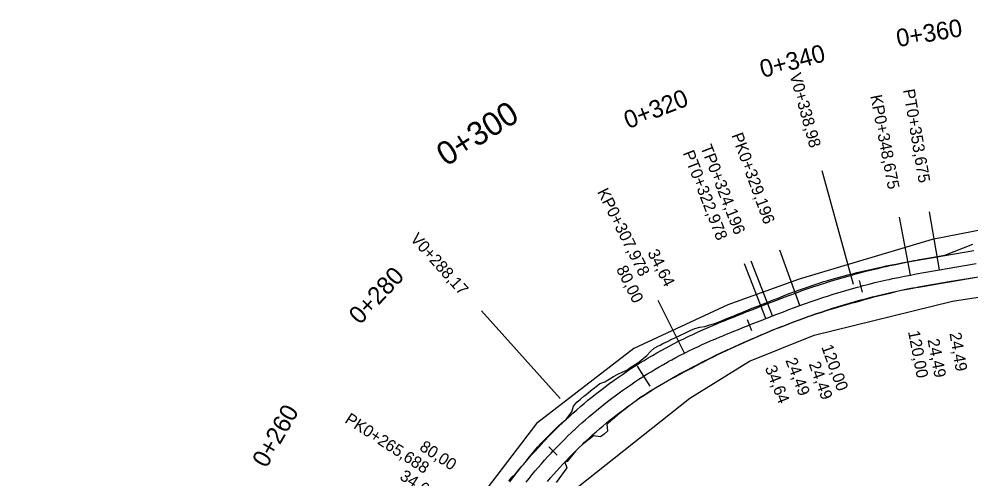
# Model space of a CAD drawing. Extents: x -636600 to -628587, y -1090963 to -1085869.
# Drawn here: x -635071.7 to -634910.1, y -1088714.1 to -1088635.9 of the extents above; entities that cross this region are included whole.
import ezdxf

# ---------------------------------------------------------------- set-up
doc = ezdxf.new("R2010")
doc.units = 0
for name, color, linetype in [('01_PARCELY_NÁVRH_PC', 7, 'Continuous'), ('HEKTOMETRY100', 7, 'Continuous'), ('HEKTOMETRY20', 7, 'Continuous'), ('HL_BODY', 7, 'Continuous'), ('POLOMERY', 7, 'Continuous'), ('situace_osa', 7, 'Continuous'), ('situace_těleso', 7, 'Continuous'), ('situace_vozovka', 7, 'Continuous'), ('VRCHOLY', 7, 'Continuous')]:
    doc.layers.add(name, color=color, linetype=linetype)

msp = doc.modelspace()

# ---------------------------------------------------------------- linework, layer by layer
at = {"layer": '01_PARCELY_NÁVRH_PC'}
for points in [[(-634861.29, -1088662.55), (-634916.65, -1088673.39), (-634939.28, -1088680.12), (-634951.36, -1088684.51), (-634967.33, -1088691.91), (-634983.87, -1088704.68), (-634995.51, -1088719.97), (-635021.98, -1088768.35), (-635040.92, -1088797.21), (-635078.05, -1088850.49), (-635098.99, -1088876.35), (-635105.07, -1088879.12), (-635110.88, -1088888.39), (-635119.1, -1088902.88), (-635126.27, -1088922.85), (-635127.59, -1088927.58), (-635130.38, -1088937.08), (-635132.64, -1088944.55), (-635134.08, -1088948.9), (-635141.78, -1088965.52), (-635145.13, -1088972.03), (-635147.95, -1088976.12), (-635154.73, -1088985.94)], [(-635153.56, -1088999.63), (-635131.9, -1088967.9), (-635114.47, -1088929.52), (-635113.55, -1088922.94), (-635105.31, -1088903.63), (-635101.54, -1088905.22), (-635094.81, -1088889.19), (-635080.24, -1088867.26), (-635022.41, -1088789.13), (-635007.04, -1088763.27), (-634984.89, -1088721.83), (-634957.8, -1088700.36), (-634947.7, -1088694.08), (-634936.69, -1088689.67), (-634913.24, -1088683.86), (-634889.39, -1088680.18)]]:
    msp.add_lwpolyline(points, dxfattribs=at)
at = {"layer": 'HEKTOMETRY100'}
msp.add_lwpolyline([(-634966.74, -1088694.94), (-634964.59, -1088698.32)], dxfattribs=at)
at = {"layer": 'HEKTOMETRY20'}
for points in [[(-634929.08, -1088680.38), (-634928.57, -1088682.31)], [(-634948.07, -1088686.98), (-634947.34, -1088688.84)], [(-634981.78, -1088708.64), (-634980.32, -1088710.02)]]:
    msp.add_lwpolyline(points, dxfattribs=at)
at = {"layer": 'HL_BODY'}
for points in [[(-634915.45, -1088678.55), (-634917.11, -1088668.69)], [(-634920.37, -1088679.42), (-634922.24, -1088669.59)], [(-634939.13, -1088684.6), (-634942.56, -1088675.21)], [(-634944.93, -1088686.82), (-634948.56, -1088677.51)], [(-634943.8, -1088686.38), (-634947.43, -1088677.06)], [(-634958.73, -1088692.7), (-634963.21, -1088683.77)]]:
    msp.add_lwpolyline(points, dxfattribs=at)
at = {"layer": 'POLOMERY'}
for points in [[(-634915.45, -1088678.55), (-634917.11, -1088668.69)], [(-634920.37, -1088679.42), (-634922.24, -1088669.59)], [(-634939.13, -1088684.6), (-634942.56, -1088675.21)], [(-634944.93, -1088686.82), (-634948.56, -1088677.51)], [(-634943.8, -1088686.38), (-634947.43, -1088677.06)], [(-634958.73, -1088692.7), (-634963.21, -1088683.77)]]:
    msp.add_lwpolyline(points, dxfattribs=at)
at = {"layer": 'situace_osa'}
msp.add_lwpolyline([(-634985.62, -1088714.62), (-634985.11, -1088713.99), (-634984.6, -1088713.35), (-634984.36, -1088713.07), (-634984.08, -1088712.73), (-634983.55, -1088712.11), (-634983.02, -1088711.49), (-634982.48, -1088710.89), (-634981.93, -1088710.28), (-634981.38, -1088709.68), (-634981.05, -1088709.33), (-634980.82, -1088709.09), (-634980.26, -1088708.5), (-634979.69, -1088707.92), (-634979.12, -1088707.35), (-634978.54, -1088706.78), (-634977.95, -1088706.22), (-634977.51, -1088705.8), (-634977.36, -1088705.66), (-634976.76, -1088705.11), (-634976.16, -1088704.56), (-634975.55, -1088704.02), (-634974.93, -1088703.49), (-634974.31, -1088702.96), (-634973.75, -1088702.5), (-634973.69, -1088702.44), (-634973.06, -1088701.93), (-634972.42, -1088701.42), (-634971.78, -1088700.92), (-634971.14, -1088700.43), (-634970.48, -1088699.94), (-634969.83, -1088699.46), (-634969.8, -1088699.44), (-634969.17, -1088698.98), (-634968.5, -1088698.52), (-634967.83, -1088698.06), (-634967.16, -1088697.6), (-634966.48, -1088697.15), (-634965.8, -1088696.71), (-634965.67, -1088696.63), (-634965.11, -1088696.28), (-634964.41, -1088695.85), (-634963.72, -1088695.44), (-634963.02, -1088695.02), (-634962.31, -1088694.62), (-634961.6, -1088694.22), (-634961.36, -1088694.09), (-634960.89, -1088693.83), (-634960.17, -1088693.45), (-634959.45, -1088693.07), (-634958.73, -1088692.7), (-634958.39, -1088692.53), (-634957.98, -1088692.33), (-634957.23, -1088691.97), (-634956.91, -1088691.82), (-634956.48, -1088691.61), (-634955.72, -1088691.26), (-634954.96, -1088690.92), (-634954.2, -1088690.58), (-634953.43, -1088690.25), (-634952.67, -1088689.92), (-634952.34, -1088689.79), (-634951.9, -1088689.6), (-634951.13, -1088689.28), (-634950.36, -1088688.97), (-634949.58, -1088688.66), (-634948.81, -1088688.35), (-634948.04, -1088688.04), (-634947.71, -1088687.91), (-634947.26, -1088687.73), (-634946.48, -1088687.43), (-634945.71, -1088687.13), (-634944.93, -1088686.82), (-634944.59, -1088686.69), (-634943.8, -1088686.38), (-634943.05, -1088686.09), (-634942.87, -1088686.02), (-634941.93, -1088685.66), (-634941, -1088685.3), (-634940.06, -1088684.95), (-634939.13, -1088684.6), (-634938.37, -1088684.32), (-634938.16, -1088684.25), (-634937.19, -1088683.91), (-634936.22, -1088683.58), (-634935.25, -1088683.26), (-634934.28, -1088682.94), (-634933.63, -1088682.74), (-634933.3, -1088682.63), (-634932.32, -1088682.34), (-634931.33, -1088682.05), (-634930.35, -1088681.76), (-634929.36, -1088681.49), (-634928.83, -1088681.35), (-634928.37, -1088681.23), (-634927.38, -1088680.97), (-634926.38, -1088680.72), (-634925.38, -1088680.48), (-634924.39, -1088680.25), (-634923.97, -1088680.16), (-634923.38, -1088680.03), (-634922.38, -1088679.82), (-634921.38, -1088679.61), (-634920.37, -1088679.42), (-634919.39, -1088679.23), (-634919.07, -1088679.17), (-634918.4, -1088679.06), (-634917.42, -1088678.88), (-634916.43, -1088678.72), (-634915.45, -1088678.55), (-634914.14, -1088678.33), (-634909.21, -1088677.49)], dxfattribs=at)
at = {"layer": 'situace_těleso'}
for points in [[(-634988.53, -1088714.46), (-634988.03, -1088713.79), (-634987.48, -1088713.28), (-634987.41, -1088713.2), (-634986.88, -1088712.56), (-634986.34, -1088711.92), (-634986.09, -1088711.63), (-634985.8, -1088711.28), (-634985.28, -1088710.63), (-634984.75, -1088709.98), (-634984.22, -1088709.33), (-634983.68, -1088708.69), (-634983.13, -1088708.06), (-634982.77, -1088707.71), (-634982.53, -1088707.47), (-634981.95, -1088706.87), (-634981.36, -1088706.28), (-634980.76, -1088705.69), (-634980.16, -1088705.11), (-634979.53, -1088704.56), (-634979.06, -1088704.15), (-634978.9, -1088704.01), (-634978.36, -1088703.35), (-634977.84, -1088702.68), (-634977.59, -1088701.69), (-634977.02, -1088701.05), (-634976.38, -1088700.51), (-634975.8, -1088700.02), (-634975.73, -1088699.96), (-634975.08, -1088699.43), (-634974.42, -1088698.9), (-634973.75, -1088698.37), (-634973.08, -1088697.85), (-634972.24, -1088697.58), (-634971.52, -1088697.12), (-634971.49, -1088697.11), (-634970.8, -1088696.69), (-634970.05, -1088696.29), (-634969.29, -1088695.92), (-634968.51, -1088695.57), (-634967.82, -1088695.1), (-634967.11, -1088694.65), (-634966.97, -1088694.57), (-634966.41, -1088694.19), (-634965.77, -1088693.62), (-634965.12, -1088693.08), (-634964.52, -1088692.43), (-634963.88, -1088691.85), (-634963.13, -1088691.47), (-634962.87, -1088691.33), (-634962.38, -1088691.08), (-634961.62, -1088690.7), (-634960.86, -1088690.33), (-634960.1, -1088689.96), (-634959.74, -1088689.8), (-634959.32, -1088689.6), (-634958.54, -1088689.23), (-634958.2, -1088689.08), (-634957.75, -1088688.88), (-634956.97, -1088688.53), (-634956.13, -1088688.3), (-634955.25, -1088688.18), (-634954.44, -1088687.9), (-634953.63, -1088687.64), (-634953.29, -1088687.53), (-634952.83, -1088687.36), (-634952.05, -1088687.04), (-634951.27, -1088686.72), (-634950.49, -1088686.41), (-634949.71, -1088686.09), (-634948.93, -1088685.77), (-634948.6, -1088685.63), (-634948.16, -1088685.45), (-634947.38, -1088685.14), (-634946.6, -1088684.83), (-634945.83, -1088684.52), (-634945.49, -1088684.39), (-634944.7, -1088684.07), (-634943.95, -1088683.77), (-634943.77, -1088683.7), (-634942.83, -1088683.33), (-634941.89, -1088682.96), (-634940.95, -1088682.59), (-634939.99, -1088682.23), (-634939.22, -1088681.94), (-634939.01, -1088681.86), (-634938.02, -1088681.53), (-634937.03, -1088681.2), (-634936.03, -1088680.87), (-634935.04, -1088680.55), (-634934.38, -1088680.34), (-634934.04, -1088680.24), (-634933.03, -1088679.94), (-634932.02, -1088679.68), (-634931.01, -1088679.41), (-634929.99, -1088679.16), (-634929.45, -1088679.02), (-634928.98, -1088678.91), (-634927.96, -1088678.67), (-634926.94, -1088678.43), (-634925.92, -1088678.2), (-634924.9, -1088677.98), (-634924.47, -1088677.89), (-634923.88, -1088677.77), (-634922.85, -1088677.56), (-634921.83, -1088677.36), (-634920.8, -1088677.17), (-634919.8, -1088676.98), (-634919.47, -1088676.93), (-634918.8, -1088676.81), (-634917.81, -1088676.63), (-634916.81, -1088676.47), (-634915.83, -1088676.29), (-634914.52, -1088676.06), (-634909.77, -1088674.19)], [(-634908.82, -1088679.81), (-634913.75, -1088680.62), (-634915.06, -1088680.85), (-634916.04, -1088681.02), (-634917.02, -1088681.19), (-634918, -1088681.37), (-634918.65, -1088681.49), (-634918.96, -1088681.55), (-634919.94, -1088681.68), (-634920.93, -1088681.83), (-634921.91, -1088682.07), (-634922.89, -1088682.3), (-634923.46, -1088682.44), (-634923.87, -1088682.54), (-634924.84, -1088682.78), (-634925.82, -1088683.02), (-634926.79, -1088683.27), (-634927.76, -1088683.53), (-634928.21, -1088683.65), (-634928.73, -1088683.79), (-634929.7, -1088684.07), (-634930.67, -1088684.34), (-634931.63, -1088684.63), (-634932.6, -1088684.91), (-634932.92, -1088685), (-634933.56, -1088685.19), (-634934.52, -1088685.48), (-634935.48, -1088685.78), (-634936.44, -1088686.09), (-634937.39, -1088686.42), (-634937.59, -1088686.49), (-634938.34, -1088686.75), (-634939.26, -1088687.08), (-634940.19, -1088687.43), (-634941.11, -1088687.79), (-634942.04, -1088688.15), (-634942.22, -1088688.22), (-634942.97, -1088688.51), (-634943.76, -1088688.82), (-634944.1, -1088688.96), (-634944.87, -1088689.29), (-634945.63, -1088689.61), (-634946.39, -1088689.94), (-634946.83, -1088690.13), (-634947.15, -1088690.27), (-634947.91, -1088690.6), (-634948.67, -1088690.94), (-634949.42, -1088691.28), (-634950.17, -1088691.62), (-634950.91, -1088691.96), (-634951.34, -1088692.16), (-634951.66, -1088692.31), (-634952.4, -1088692.66), (-634953.13, -1088693.01), (-634953.86, -1088693.37), (-634954.59, -1088693.74), (-634955.31, -1088694.1), (-634955.72, -1088694.32), (-634956.03, -1088694.48), (-634956.74, -1088694.86), (-634957.13, -1088695.07), (-634957.45, -1088695.23), (-634958.15, -1088695.59), (-634958.84, -1088695.96), (-634959.54, -1088696.33), (-634959.99, -1088696.58), (-634960.22, -1088696.71), (-634960.91, -1088697.08), (-634961.6, -1088697.46), (-634962.29, -1088697.84), (-634962.96, -1088698.24), (-634963.64, -1088698.64), (-634964.18, -1088698.97), (-634964.31, -1088699.05), (-634964.98, -1088699.46), (-634965.64, -1088699.89), (-634966.29, -1088700.32), (-634966.93, -1088700.78), (-634967.56, -1088701.25), (-634968.16, -1088701.7), (-634968.18, -1088701.72), (-634968.8, -1088702.21), (-634969.42, -1088702.7), (-634970.03, -1088703.19), (-634970.63, -1088703.69), (-634971.23, -1088704.2), (-634971.82, -1088704.71), (-634971.89, -1088704.76), (-634971.79, -1088705.97), (-634972.39, -1088706.46), (-634972.98, -1088706.95), (-634974.2, -1088706.75), (-634974.82, -1088707.24), (-634975.42, -1088707.74), (-634975.58, -1088707.86), (-634976.03, -1088708.24), (-634976.62, -1088708.75), (-634977.15, -1088709.33), (-634977.67, -1088709.93), (-634978.17, -1088710.53), (-634978.67, -1088711.14), (-634979.02, -1088711.24), (-634978.68, -1088712.2), (-634979.15, -1088712.82), (-634979.61, -1088713.45), (-634980.07, -1088714.07), (-634980.53, -1088714.7)]]:
    msp.add_lwpolyline(points, dxfattribs=at)
at = {"layer": 'situace_vozovka'}
for points in [[(-634988.41, -1088714.55), (-634987.9, -1088713.89), (-634987.45, -1088713.31), (-634987.38, -1088713.23), (-634986.86, -1088712.57), (-634986.33, -1088711.92), (-634986.09, -1088711.64), (-634985.8, -1088711.28), (-634985.26, -1088710.64), (-634984.71, -1088710.01), (-634984.16, -1088709.39), (-634983.59, -1088708.77), (-634983.03, -1088708.15), (-634982.69, -1088707.79), (-634982.46, -1088707.54), (-634981.88, -1088706.94), (-634981.29, -1088706.34), (-634980.7, -1088705.75), (-634980.1, -1088705.16), (-634979.5, -1088704.59), (-634979.05, -1088704.16), (-634978.89, -1088704.01), (-634978.28, -1088703.45), (-634977.66, -1088702.89), (-634977.03, -1088702.33), (-634976.4, -1088701.78), (-634975.76, -1088701.24), (-634975.19, -1088700.76), (-634975.12, -1088700.71), (-634974.47, -1088700.18), (-634973.82, -1088699.66), (-634973.16, -1088699.14), (-634972.49, -1088698.63), (-634971.83, -1088698.13), (-634971.15, -1088697.64), (-634971.12, -1088697.62), (-634970.47, -1088697.15), (-634969.79, -1088696.67), (-634969.1, -1088696.2), (-634968.41, -1088695.73), (-634967.71, -1088695.27), (-634967, -1088694.82), (-634966.87, -1088694.73), (-634966.3, -1088694.37), (-634965.58, -1088693.93), (-634964.87, -1088693.5), (-634964.15, -1088693.08), (-634963.42, -1088692.66), (-634962.69, -1088692.25), (-634962.45, -1088692.12), (-634961.96, -1088691.85), (-634961.22, -1088691.46), (-634960.48, -1088691.07), (-634959.74, -1088690.69), (-634959.39, -1088690.52), (-634958.97, -1088690.31), (-634958.2, -1088689.94), (-634957.87, -1088689.78), (-634957.43, -1088689.57), (-634956.65, -1088689.22), (-634955.88, -1088688.87), (-634955.1, -1088688.52), (-634954.32, -1088688.18), (-634953.54, -1088687.85), (-634953.21, -1088687.71), (-634952.76, -1088687.52), (-634951.98, -1088687.2), (-634951.2, -1088686.88), (-634950.42, -1088686.57), (-634949.64, -1088686.26), (-634948.86, -1088685.95), (-634948.53, -1088685.82), (-634948.08, -1088685.64), (-634947.3, -1088685.33), (-634946.53, -1088685.03), (-634945.75, -1088684.73), (-634945.4, -1088684.59), (-634944.61, -1088684.29), (-634943.86, -1088683.99), (-634943.68, -1088683.92), (-634942.74, -1088683.56), (-634941.8, -1088683.2), (-634940.85, -1088682.84), (-634939.9, -1088682.49), (-634939.13, -1088682.21), (-634938.92, -1088682.13), (-634937.93, -1088681.78), (-634936.94, -1088681.45), (-634935.95, -1088681.12), (-634934.96, -1088680.8), (-634934.3, -1088680.59), (-634933.96, -1088680.48), (-634932.96, -1088680.18), (-634931.96, -1088679.88), (-634930.96, -1088679.6), (-634929.95, -1088679.32), (-634929.41, -1088679.17), (-634928.94, -1088679.05), (-634927.93, -1088678.79), (-634926.92, -1088678.54), (-634925.9, -1088678.29), (-634924.88, -1088678.06), (-634924.46, -1088677.96), (-634923.86, -1088677.83), (-634922.84, -1088677.62), (-634921.82, -1088677.41), (-634920.79, -1088677.21), (-634919.79, -1088677.02), (-634919.47, -1088676.96), (-634918.8, -1088676.84), (-634917.8, -1088676.67), (-634916.81, -1088676.5), (-634915.82, -1088676.33), (-634914.52, -1088676.11), (-634909.59, -1088675.27)], [(-634981.98, -1088714.49), (-634981.47, -1088713.89), (-634980.96, -1088713.3), (-634980.43, -1088712.71), (-634979.91, -1088712.13), (-634979.38, -1088711.55), (-634979.06, -1088711.21), (-634978.84, -1088710.98), (-634978.29, -1088710.41), (-634977.74, -1088709.85), (-634977.19, -1088709.3), (-634976.63, -1088708.75), (-634976.06, -1088708.2), (-634975.64, -1088707.8), (-634975.49, -1088707.66), (-634974.91, -1088707.13), (-634974.33, -1088706.6), (-634973.74, -1088706.08), (-634973.15, -1088705.57), (-634972.55, -1088705.06), (-634972.01, -1088704.61), (-634971.95, -1088704.56), (-634971.34, -1088704.06), (-634970.72, -1088703.57), (-634970.1, -1088703.09), (-634969.48, -1088702.61), (-634968.85, -1088702.14), (-634968.22, -1088701.68), (-634968.19, -1088701.66), (-634967.58, -1088701.22), (-634966.94, -1088700.77), (-634966.29, -1088700.32), (-634965.64, -1088699.88), (-634964.98, -1088699.45), (-634964.32, -1088699.03), (-634964.2, -1088698.94), (-634963.66, -1088698.61), (-634962.99, -1088698.19), (-634962.32, -1088697.79), (-634961.64, -1088697.39), (-634960.96, -1088697), (-634960.27, -1088696.62), (-634960.04, -1088696.49), (-634959.59, -1088696.24), (-634958.89, -1088695.87), (-634958.2, -1088695.51), (-634957.5, -1088695.15), (-634957.17, -1088694.99), (-634956.78, -1088694.78), (-634956.07, -1088694.4), (-634955.76, -1088694.24), (-634955.35, -1088694.03), (-634954.62, -1088693.67), (-634953.89, -1088693.31), (-634953.16, -1088692.95), (-634952.42, -1088692.6), (-634951.68, -1088692.26), (-634951.36, -1088692.11), (-634950.93, -1088691.92), (-634950.19, -1088691.58), (-634949.43, -1088691.24), (-634948.68, -1088690.91), (-634947.92, -1088690.57), (-634947.16, -1088690.24), (-634946.84, -1088690.1), (-634946.4, -1088689.92), (-634945.64, -1088689.59), (-634944.88, -1088689.26), (-634944.11, -1088688.93), (-634943.77, -1088688.79), (-634942.98, -1088688.48), (-634942.23, -1088688.19), (-634942.05, -1088688.12), (-634941.12, -1088687.76), (-634940.2, -1088687.4), (-634939.27, -1088687.05), (-634938.35, -1088686.71), (-634937.61, -1088686.44), (-634937.41, -1088686.37), (-634936.46, -1088686.04), (-634935.51, -1088685.71), (-634934.55, -1088685.39), (-634933.59, -1088685.08), (-634932.96, -1088684.88), (-634932.63, -1088684.78), (-634931.67, -1088684.49), (-634930.71, -1088684.21), (-634929.74, -1088683.93), (-634928.77, -1088683.66), (-634928.25, -1088683.52), (-634927.8, -1088683.4), (-634926.82, -1088683.15), (-634925.85, -1088682.91), (-634924.87, -1088682.67), (-634923.89, -1088682.45), (-634923.48, -1088682.36), (-634922.91, -1088682.23), (-634921.92, -1088682.02), (-634920.94, -1088681.82), (-634919.95, -1088681.63), (-634918.98, -1088681.45), (-634918.67, -1088681.39), (-634918.01, -1088681.27), (-634917.04, -1088681.1), (-634916.06, -1088680.93), (-634915.07, -1088680.77), (-634913.76, -1088680.55), (-634908.83, -1088679.71)]]:
    msp.add_lwpolyline(points, dxfattribs=at)
at = {"layer": 'VRCHOLY'}
for points in [[(-634930.02, -1088681.01), (-634935.35, -1088661.74)], [(-634979.85, -1088700.43), (-634993.18, -1088685.52)]]:
    msp.add_lwpolyline(points, dxfattribs=at)

# ---------------------------------------------------------------- texts
at = {"layer": 'HEKTOMETRY100'}
msp.add_text('0+300', height=4, rotation=32.3752, dxfattribs=at).set_placement((-634999.2, -1088661.06))
at = {"layer": 'HEKTOMETRY20'}
for s, rotation, p in [('0+360', 9.6019, (-634922.49, -1088640.69)), ('0+340', 14.9375, (-634945.47, -1088645.94)), ('0+320', 21.5016, (-634968.29, -1088654.64)), ('0+280', 46.6991, (-635013.84, -1088687.99)), ('0+260', 60.2506, (-635029.71, -1088712.36))]:
    msp.add_text(s, height=3, rotation=rotation, dxfattribs=at).set_placement(p)
at = {"layer": 'HL_BODY'}
for s, rotation, p in [('PT0+353,675', 279.6019, (-634921.63, -1088647.97)), ('KP0+348,675', 280.7956, (-634927.19, -1088648.98)), ('PK0+329,196', 290.0962, (-634950.78, -1088655.66)), ('PT0+322,978', 291.2899, (-634959.05, -1088658.68)), ('TP0+324,196', 291.2899, (-634956.05, -1088657.69)), ('KP0+307,978', 296.6614, (-634973.61, -1088665.29)), ('PK0+265,688', 326.949, (-635016.56, -1088704.4))]:
    msp.add_text(s, height=2, rotation=rotation, dxfattribs=at).set_placement(p)
at = {"layer": 'POLOMERY'}
for s, rotation, p in [('34,64', 296.6614, (-634965.06, -1088675.63)), ('80,00', 296.6614, (-634970.38, -1088678.41)), ('120,00', 280.7956, (-634920.78, -1088689.04)), ('24,49', 280.7956, (-634917.47, -1088690.43)), ('24,49', 279.6019, (-634913.74, -1088689.32)), ('120,00', 290.0962, (-634935.53, -1088691.64)), ('24,49', 291.2899, (-634941.63, -1088693.92)), ('34,64', 291.2899, (-634945.11, -1088695.22)), ('24,49', 290.0962, (-634937.67, -1088694.53)), ('80,00', 326.949, (-635003.88, -1088709.07)), ('34,64', 326.949, (-635007.23, -1088714.05))]:
    msp.add_text(s, height=2, rotation=rotation, dxfattribs=at).set_placement(p)
at = {"layer": 'VRCHOLY'}
for s, rotation, p in [('V0+338,98', 285.4459, (-634940.9, -1088645.41)), ('V0+288,17', 311.8052, (-635005.4, -1088673.36))]:
    msp.add_text(s, height=2, rotation=rotation, dxfattribs=at).set_placement(p)

doc.saveas('drawing.dxf')
